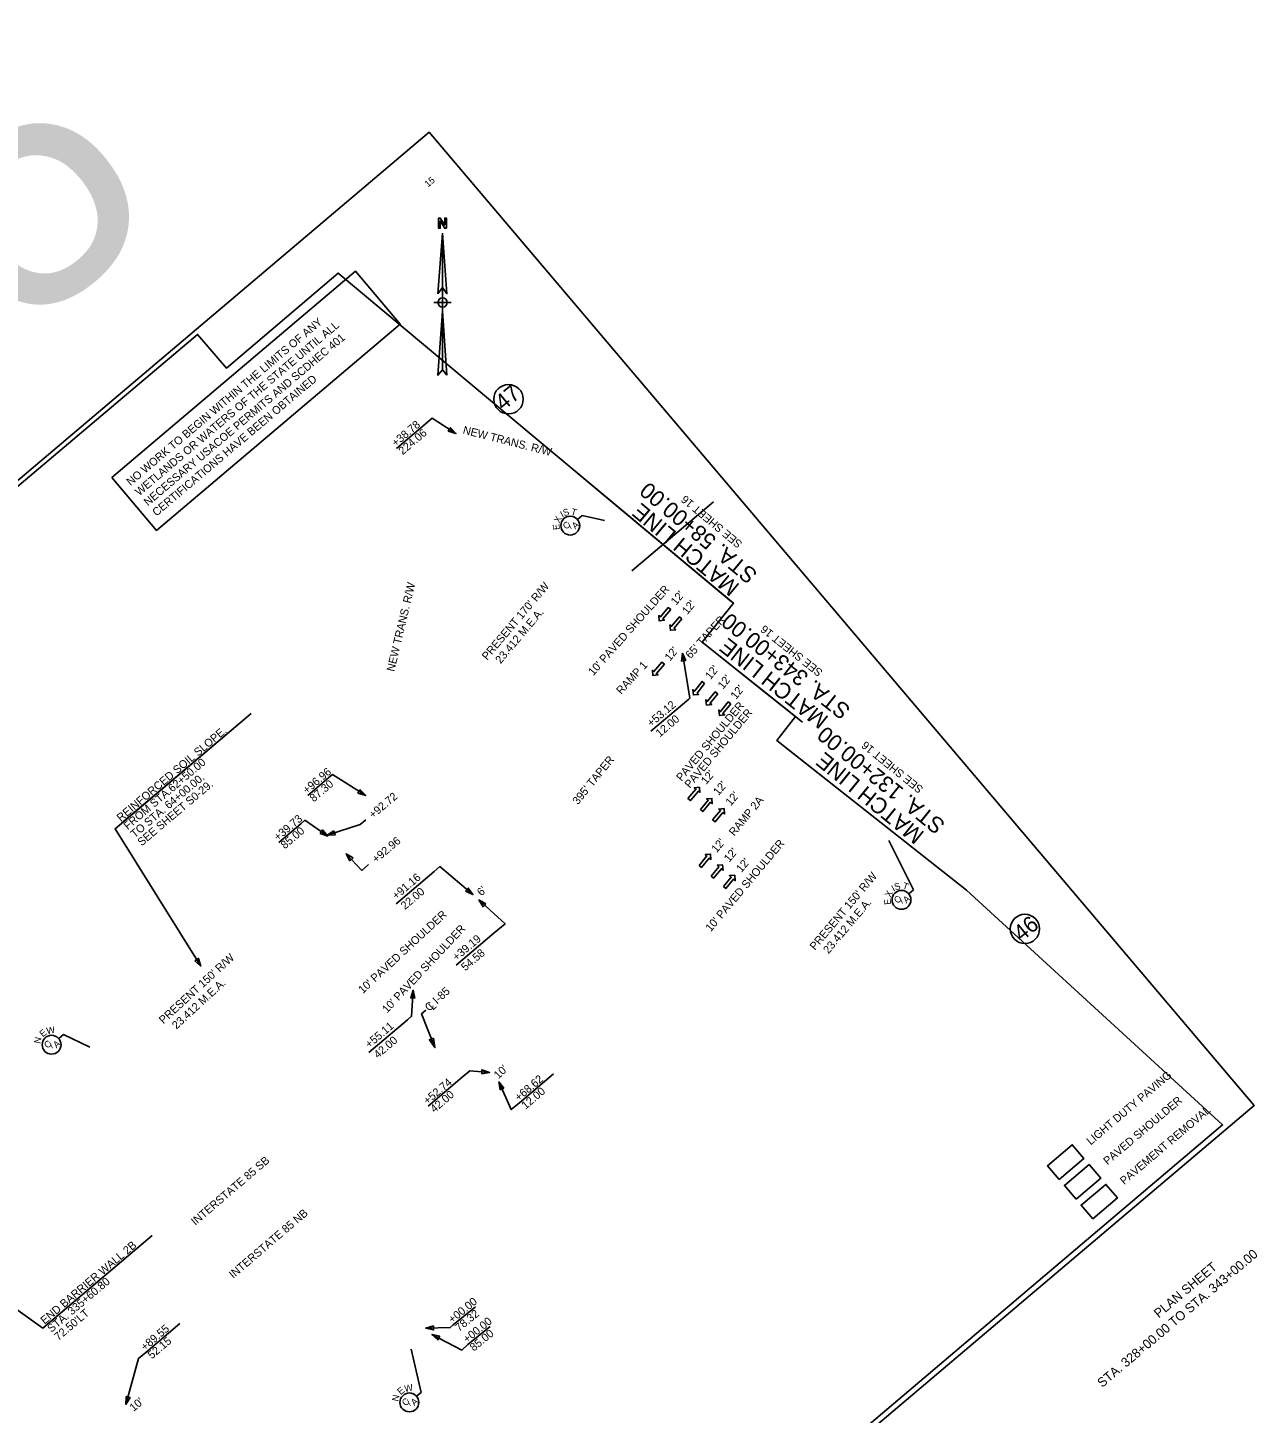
# Model space of a CAD drawing. Extents: x 1613433 to 1615331, y 1095338 to 1097615.
# Drawn here: x 1614410 to 1615331, y 1096576 to 1097615 of the extents above; entities that cross this region are included whole.
import ezdxf

# ---------------------------------------------------------------- set-up
doc = ezdxf.new("R2010")
doc.units = 0
for name, color, linetype in [('RD_EX_Bldg', 7, 'Continuous'), ('RD_EX_BldgApp_txCode', 7, 'Continuous'), ('RD_EX_DR_Pipe', 7, 'Continuous'), ('RD_EX_DV_Prop', 7, 'Continuous'), ('RD_EX_Fence_ChLk', 7, 'Continuous'), ('RD_EX_GuardRail', 7, 'Continuous'), ('RD_EX_H2O', 7, 'Continuous'), ('RD_EX_Misc', 7, 'Continuous'), ('RD_EX_RW', 7, 'Continuous'), ('RD_HC_TX_Rel_Sta50', 7, 'Continuous'), ('RD_PD_Final_TX', 7, 'Continuous'), ('RD_PD_RW_TX', 7, 'Continuous'), ('RD_SHT_DR_TX_FINAL', 7, 'Continuous'), ('RD_SHT_UT_TX_PREL', 7, 'Continuous')]:
    doc.layers.add(name, color=color, linetype=linetype)

msp = doc.modelspace()

# ---------------------------------------------------------------- linework, layer by layer
at = {"layer": 'RD_EX_Bldg'}
for p, q in [((1614704.4, 1097314.6), (1614686.3, 1097299.2)), ((1614635.6, 1097052.4), (1614619.7, 1097038.9)), ((1614614.5, 1097017.8), (1614598, 1097003.8)), ((1614745.4, 1096655.6), (1614728.7, 1096642.1)), ((1614756.4, 1096640.8), (1614739.7, 1096627.3))]:
    msp.add_line(p, q, dxfattribs=at)
for points in [[(1614704.4, 1097314.6), (1614712.9, 1097321.8), (1614730.8, 1097310.3)], [(1614635.6, 1097052.4), (1614638.2, 1097054.6), (1614663.2, 1097038.9)], [(1614614.5, 1097017.8), (1614617.6, 1097020.4), (1614634.8, 1097008.5)], [(1614728.7, 1096642.1), (1614726.6, 1096640), (1614708.2, 1096639.6)], [(1614739.7, 1096627.3), (1614735.2, 1096623.1), (1614712.8, 1096634.8)]]:
    msp.add_lwpolyline(points, dxfattribs=at)
for points in [[(1614725.1, 1097312.1), (1614730.8, 1097310.3), (1614726.8, 1097314.7)], [(1614657.4, 1097040.6), (1614663.2, 1097038.9), (1614659.1, 1097043.3)], [(1614629.1, 1097010.5), (1614634.8, 1097008.5), (1614630.9, 1097013.1)], [(1614713.9, 1096641.3), (1614708.2, 1096639.6), (1614714, 1096638.2)], [(1614718.7, 1096633.5), (1614712.8, 1096634.8), (1614717.2, 1096630.8)]]:
    msp.add_lwpolyline(points, close=True, dxfattribs=at)
at = {"layer": 'RD_EX_BldgApp_txCode'}
for p, q in [((1614433.2, 1096856.7), (1614436.7, 1096859.7)), ((1614436.7, 1096859.7), (1614456.4, 1096850.2)), ((1614704.8, 1096591.4), (1614697.2, 1096623.8)), ((1614701.3, 1096588.5), (1614704.8, 1096591.4))]:
    msp.add_line(p, q, dxfattribs=at)
for centre in [(1614427.8, 1096852.1), (1614695.9, 1096583.9)]:
    msp.add_circle(centre, 7.08, dxfattribs=at)
at = {"layer": 'RD_EX_DR_Pipe'}
msp.add_line((1614862.7, 1097207.4), (1614923.8, 1097259.1), dxfattribs=at)
msp.add_lwpolyline([(1613636.5, 1096424.5), (1613794.6, 1096211.8), (1613781.7, 1096202.2), (1613853.4, 1096105.7), (1613849.9, 1096103.1), (1613959.1, 1095956.1), (1614080.2, 1095752.7), (1615305.3, 1096791.9), (1615113.5, 1096968), (1614971.2, 1097080.2), (1614985.2, 1097098.2), (1614915.3, 1097153.9), (1614938.7, 1097183.2), (1614788.8, 1097308.4), (1614642.5, 1097430.7), (1614558.9, 1097359.3), (1614537.2, 1097384.7), (1613565.8, 1096563.6)], close=True, dxfattribs=at)
msp.add_lwpolyline([(1613636.5, 1096424.5), (1613794.6, 1096211.8), (1613781.7, 1096202.2), (1613853.4, 1096105.7), (1613849.9, 1096103.1), (1613959.1, 1095956.1), (1614080.2, 1095752.7), (1615305.3, 1096791.9), (1615113.5, 1096968), (1614971.2, 1097080.2), (1614985.2, 1097098.2), (1614915.3, 1097153.9), (1614938.7, 1097183.2), (1614788.8, 1097308.4), (1614642.5, 1097430.7), (1614558.9, 1097359.3), (1614537.2, 1097384.7), (1613565.8, 1096563.6)], close=True, dxfattribs=at)
at = {"layer": 'RD_EX_DV_Prop'}
for points in [[(1614663.2, 1097020.6), (1614659, 1097017.1), (1614634.2, 1097009.1)], [(1614665.4, 1096987.1), (1614660.4, 1096982.8), (1614648.5, 1096995.2)]]:
    msp.add_lwpolyline(points, dxfattribs=at)
for points in [[(1614639.2, 1097012.4), (1614634.2, 1097009.1), (1614640.2, 1097009.4)], [(1614653.7, 1096992.1), (1614648.5, 1096995.2), (1614651.4, 1096990)]]:
    msp.add_lwpolyline(points, close=True, dxfattribs=at)
at = {"layer": 'RD_EX_Fence_ChLk'}
for p, q in [((1614821.9, 1097245.8), (1614825.4, 1097248.8)), ((1614825.4, 1097248.8), (1614842.1, 1097245.1)), ((1615073.6, 1096968.3), (1615055.1, 1097005.1)), ((1615070.1, 1096965.3), (1615073.6, 1096968.3))]:
    msp.add_line(p, q, dxfattribs=at)
for centre in [(1614816.5, 1097241.3), (1615064.7, 1096960.7)]:
    msp.add_circle(centre, 7.08, dxfattribs=at)
at = {"layer": 'RD_EX_GuardRail'}
msp.add_lwpolyline([(1613432.5, 1096453.7), (1614710.7, 1097536.3), (1615328.9, 1096806.4), (1614050.7, 1095723.8)], close=True, dxfattribs=at)
at = {"layer": 'RD_EX_H2O'}
for p, q in [((1614720.7, 1097460.5), (1614717.3, 1097415.2)), ((1614720.7, 1097419.8), (1614717.3, 1097415.2)), ((1614720.7, 1097419.8), (1614720.7, 1097402)), ((1614727.3, 1097408.6), (1614714.3, 1097408.6)), ((1614720.7, 1097402), (1614724.1, 1097354.1)), ((1614724.1, 1097354.1), (1614720.7, 1097358))]:
    msp.add_line(p, q, dxfattribs=at)
msp.add_lwpolyline([(1614723.7, 1097464.3), (1614722.4, 1097464.3), (1614719, 1097469.8), (1614719, 1097468.9), (1614719, 1097464.3), (1614717.8, 1097464.3), (1614717.8, 1097471.9), (1614719, 1097471.9), (1614722.4, 1097466.8), (1614722.4, 1097467.2), (1614722.4, 1097471.9), (1614723.7, 1097471.9), (1614723.7, 1097464.3)], dxfattribs=at)
for points in [[(1614720.7, 1097460.5), (1614724.1, 1097415.2), (1614720.7, 1097419.8)], [(1614720.7, 1097402), (1614720.7, 1097358), (1614717.3, 1097354.1)]]:
    msp.add_lwpolyline(points, close=True, dxfattribs=at)
msp.add_circle((1614720.8, 1097408.6), 3.45, dxfattribs=at)
at = {"layer": 'RD_EX_Misc'}
for centre in [(1614770.2, 1097336.1), (1615157.2, 1096938.9)]:
    msp.add_circle(centre, 11, dxfattribs=at)
at = {"layer": 'RD_EX_RW'}
for points in [[(1614891.8, 1097178.4), (1614889.9, 1097179.9), (1614884, 1097172.8), (1614882.8, 1097173.9), (1614883.2, 1097169.9), (1614887.1, 1097170.3), (1614885.9, 1097171.3)], [(1614900.2, 1097171.3), (1614898.3, 1097172.9), (1614892.4, 1097165.8), (1614891.2, 1097166.9), (1614891.6, 1097162.9), (1614895.5, 1097163.2), (1614894.3, 1097164.3)], [(1614887, 1097137.4), (1614885.1, 1097138.9), (1614879.2, 1097131.9), (1614878, 1097132.9), (1614878.4, 1097128.9), (1614882.3, 1097129.3), (1614881.1, 1097130.3)], [(1614917.2, 1097123), (1614915.3, 1097124.5), (1614909.6, 1097117.3), (1614908.3, 1097118.3), (1614908.8, 1097114.4), (1614912.7, 1097114.8), (1614911.5, 1097115.8)], [(1614927, 1097115.3), (1614925.1, 1097116.8), (1614919.4, 1097109.6), (1614918.1, 1097110.7), (1614918.6, 1097106.7), (1614922.5, 1097107.1), (1614921.3, 1097108.1)], [(1614936.7, 1097107.6), (1614934.8, 1097109.1), (1614929.1, 1097101.9), (1614927.8, 1097103), (1614928.2, 1097099), (1614932.2, 1097099.4), (1614930.9, 1097100.4)], [(1614904.7, 1097036.7), (1614906.6, 1097035.2), (1614912.5, 1097042.2), (1614913.7, 1097041.2), (1614913.3, 1097045.1), (1614909.4, 1097044.8), (1614910.6, 1097043.8)], [(1614914, 1097028.4), (1614915.8, 1097026.9), (1614921.7, 1097033.9), (1614922.9, 1097032.9), (1614922.6, 1097036.8), (1614918.6, 1097036.5), (1614919.9, 1097035.4)], [(1614923.2, 1097020.7), (1614925, 1097019.2), (1614930.9, 1097026.2), (1614932.1, 1097025.1), (1614931.8, 1097029.1), (1614927.8, 1097028.8), (1614929.1, 1097027.7)], [(1614913, 1096986.5), (1614914.8, 1096985), (1614920.7, 1096992), (1614921.9, 1096991), (1614921.6, 1096995), (1614917.6, 1096994.6), (1614918.9, 1096993.6)], [(1614922, 1096978.5), (1614923.8, 1096976.9), (1614929.7, 1096984), (1614931, 1096982.9), (1614930.6, 1096986.9), (1614926.6, 1096986.6), (1614927.9, 1096985.5)], [(1614931.2, 1096970.8), (1614933, 1096969.2), (1614938.9, 1096976.3), (1614940.1, 1096975.2), (1614939.8, 1096979.2), (1614935.8, 1096978.9), (1614937.1, 1096977.8)]]:
    msp.add_lwpolyline(points, close=True, dxfattribs=at)
at = {"layer": 'RD_HC_TX_Rel_Sta50'}
msp.add_lwpolyline([(1614715.1, 1096850), (1614705.1, 1096875.2), (1614708.2, 1096878.1)], dxfattribs=at)
msp.add_lwpolyline([(1614714.1, 1096857.1), (1614710.9, 1096855.8), (1614715.1, 1096850)], close=True, dxfattribs=at)
at = {"layer": 'RD_SHT_DR_TX_FINAL'}
for p, q in [((1614937.1, 1097184.5), (1614822.2, 1097280.5)), ((1615113.5, 1096968), (1614975, 1097077.2))]:
    msp.add_line(p, q, dxfattribs=at)
msp.add_lwpolyline([(1614990.4, 1097094), (1614959.1, 1097119), (1614915.3, 1097153.9)], dxfattribs=at)
at = {"layer": 'RD_SHT_UT_TX_PREL'}
for p, q in [((1614905.4, 1097111.3), (1614876.9, 1097087.2)), ((1614577.3, 1097100.4), (1614480.3, 1097018.2)), ((1614714.5, 1096982), (1614685.9, 1096957.8)), ((1614759.5, 1096935.9), (1614731.1, 1096911.8)), ((1614694.4, 1096870.7), (1614665.6, 1096846.3)), ((1614735.6, 1096827.7), (1614710.1, 1096806.1)), ((1614803.9, 1096830.2), (1614778.5, 1096808.6)), ((1614503.1, 1096709), (1614423.2, 1096641.3)), ((1614523.8, 1096643), (1614498.3, 1096621.4))]:
    msp.add_line(p, q, dxfattribs=at)
for points in [[(1614473, 1097277.3), (1614655.6, 1097432), (1614689.1, 1097392.4), (1614506.5, 1097237.7)], [(1614903, 1097140.1), (1614900.5, 1097145.6), (1614899.9, 1097139.6)], [(1614738.1, 1096967.2), (1614743.5, 1096964.6), (1614740.1, 1096969.5)], [(1614753.3, 1096957.8), (1614748, 1096960.6), (1614751.2, 1096955.5)], [(1614535.2, 1096915.1), (1614539.6, 1096911), (1614537.9, 1096916.8)], [(1614700, 1096887), (1614698.8, 1096892.9), (1614696.9, 1096887.2)], [(1614750.1, 1096830.2), (1614756, 1096831.3), (1614750.3, 1096833.3)], [(1614766.8, 1096819.5), (1614763, 1096824.2), (1614764, 1096818.3)], [(1615182.9, 1096751.1), (1615201.4, 1096766.8), (1615192.7, 1096777.1), (1615174.2, 1096761.4)], [(1615195.5, 1096736.3), (1615214, 1096752), (1615205.3, 1096762.3), (1615186.8, 1096746.6)], [(1615208, 1096721.5), (1615226.5, 1096737.2), (1615217.9, 1096747.4), (1615199.3, 1096731.8)], [(1614483.6, 1096588.4), (1614483.5, 1096582.4), (1614486.6, 1096587.6)]]:
    msp.add_lwpolyline(points, close=True, dxfattribs=at)
for points in [[(1614905.4, 1097111.3), (1614906.2, 1097112), (1614900.5, 1097145.6)], [(1614577.3, 1097100.4), (1614475.4, 1097014), (1614539.6, 1096911)], [(1614714.5, 1096982), (1614718.8, 1096985.7), (1614743.5, 1096964.6)], [(1614759.5, 1096935.9), (1614767.6, 1096942.7), (1614748, 1096960.6)], [(1614694.4, 1096870.7), (1614697.6, 1096873.4), (1614698.8, 1096892.9)], [(1614735.6, 1096827.7), (1614741.2, 1096832.4), (1614756, 1096831.3)], [(1614778.5, 1096808.6), (1614772.3, 1096803.5), (1614763, 1096824.2)], [(1615182.9, 1096751.1), (1615201.4, 1096766.8), (1615192.7, 1096777.1), (1615174.2, 1096761.4), (1615182.9, 1096751.1)], [(1615195.5, 1096736.3), (1615214, 1096752), (1615205.3, 1096762.3), (1615186.8, 1096746.6), (1615195.5, 1096736.3)], [(1615208, 1096721.5), (1615226.5, 1096737.2), (1615217.9, 1096747.4), (1615199.3, 1096731.8), (1615208, 1096721.5)], [(1614503.1, 1096709), (1614421.3, 1096639.6), (1614385.8, 1096664.9)], [(1614498.3, 1096621.4), (1614493, 1096616.9), (1614483.5, 1096582.4)]]:
    msp.add_lwpolyline(points, dxfattribs=at)

# ---------------------------------------------------------------- texts
at = {"layer": 'RD_EX_Bldg'}
for s, rotation, p in [('+38.78', 40.265, (1614685.7, 1097300.1)), ('224.06', 40.265, (1614690.9, 1097294)), ('+96.96', 40.265, (1614619.1, 1097039.8)), ('87.30', 40.265, (1614624.3, 1097033.7)), ('+39.73', 40.265, (1614597.4, 1097004.6)), ('85.00', 40.265, (1614602.6, 1096998.5)), ('+00.00', 39.1575, (1614728.1, 1096642.9)), ('78.32', 39.1575, (1614733.2, 1096636.7)), ('+00.00', 39.1575, (1614739.2, 1096628.1)), ('85.00', 39.1575, (1614744.2, 1096621.9))]:
    msp.add_text(s, height=6, rotation=rotation, dxfattribs=at).set_placement(p)
at = {"layer": 'RD_EX_BldgApp_txCode'}
for s, rotation, p in [('W', 11.0644, (1614424.5, 1096859.9)), ('N', 79.1766, (1614419.4, 1096852.6)), ('E', 40.2633, (1614421.3, 1096857.5)), ('C', 40.2634, (1614424.7, 1096849)), ('/', 40.2634, (1614428.3, 1096849.3)), ('A', 40.2634, (1614431.5, 1096849.2)), ('E', 40.2633, (1614689.4, 1096589.3)), ('W', 11.0644, (1614692.7, 1096591.7)), ('N', 79.1766, (1614687.6, 1096584.4)), ('C', 40.2634, (1614692.9, 1096580.8)), ('/', 40.2634, (1614696.5, 1096581.1)), ('A', 40.2634, (1614699.6, 1096581))]:
    msp.add_text(s, height=5, rotation=rotation, dxfattribs=at).set_placement(p)
at = {"layer": 'RD_EX_DV_Prop'}
for s, rotation, p in [("PRESENT 170' R/W ", 49.8309, (1614754.2, 1097140)), ('  23.412 M.E.A.', 49.8309, (1614761.4, 1097133.9)), ('+92.72', 40.265, (1614668.7, 1097021.3)), ('+92.96', 40.265, (1614671.1, 1096988)), ("PRESENT 150' R/W ", 49.8766, (1614999.9, 1096922.5)), ('  23.412 M.E.A.', 49.8766, (1615007.1, 1096916.4)), ("PRESENT 150' R/W ", 42.5813, (1614511.6, 1096867.3)), ('  23.412 M.E.A.', 42.5813, (1614518.1, 1096860.3))]:
    msp.add_text(s, height=6, rotation=rotation, dxfattribs=at).set_placement(p)
at = {"layer": 'RD_EX_Fence_ChLk'}
for s, rotation, p in [('X', 63.4064, (1614808.3, 1097242.9)), ('I', 29.3612, (1614810.6, 1097247.2)), ('S', 17.6407, (1614811.9, 1097248.3)), ('T', 344.1536, (1614816.6, 1097249.6)), ('E', 95.2192, (1614808.7, 1097238.3)), ('C', 40.2618, (1614813.4, 1097238.1)), ('/', 40.2618, (1614817.1, 1097238.5)), ('A', 40.2618, (1614820.2, 1097238.3)), ('X', 63.4064, (1615056.4, 1096962.2)), ('I', 28.2449, (1615058.8, 1096966.7)), ('S', 16.5244, (1615060.1, 1096967.8)), ('T', 341.363, (1615065.1, 1096969.2)), ('E', 96.8935, (1615057, 1096957.4)), ('C', 40.2618, (1615061.6, 1096957.6)), ('/', 40.2618, (1615065.3, 1096957.9)), ('A', 40.2618, (1615068.4, 1096957.8))]:
    msp.add_text(s, height=5, rotation=rotation, dxfattribs=at).set_placement(p)
at = {"layer": 'RD_EX_Misc'}
for s, p in [('47', (1614766.3, 1097327)), ('46', (1615154.8, 1096929.1))]:
    msp.add_text(s, height=12, rotation=39.614, dxfattribs=at).set_placement(p)
at = {"layer": 'RD_HC_TX_Rel_Sta50'}
for s, height, rotation, p in [('RAMP 1', 6, 47.4299, (1614854.7, 1097114.3)), ('RAMP 2A', 6, 50.6135, (1614939.4, 1097008.1)), ('C I-85', 6, 42.6002, (1614710.8, 1096876.7)), ('L', 6, 42.6002, (1614713.6, 1096877.6)), ('INTERSTATE 85 SB', 6, 40.585, (1614535.5, 1096716.3)), ('INTERSTATE 85 NB', 6, 40.585, (1614563.9, 1096676.5)), ('STA. 328+00.00 TO STA. 343+00.00', 6.983, 40.265, (1615215.1, 1096594.7)), ('PLAN SHEET', 6.98, 40.265, (1615257.5, 1096646.8))]:
    msp.add_text(s, height=height, rotation=rotation, dxfattribs=at).set_placement(p)
at = {"layer": 'RD_PD_Final_TX'}
msp.add_text('SHEET 15', height=200, rotation=40.265, dxfattribs=at).set_placement((1613553.3, 1096659.6))
at = {"layer": 'RD_PD_RW_TX'}
for rotation, p in [(345.6709, (1614735.6, 1097310.4)), (76.6319, (1614684.6, 1097131.5))]:
    msp.add_text('NEW TRANS. R/W', height=6, rotation=rotation, dxfattribs=at).set_placement(p)
at = {"layer": 'RD_SHT_DR_TX_FINAL'}
for s, height, rotation, p in [('STA. 58+00.00', 12, 140.1464, (1614957.6, 1097205.9)), ('SEE SHEET 16', 6, 140.1977, (1614945.9, 1097228.5)), ('MATCH LINE', 12, 140.1464, (1614944.1, 1097196.7)), ('STA. 343+00.00', 12, 141.6423, (1615027.4, 1097104.4)), ('SEE SHEET 16', 6, 141.6935, (1615006.2, 1097132.3)), ('MATCH LINE', 12, 141.6423, (1615010.8, 1097097.5)), ('STA. 132+00.00', 12, 140.8967, (1615098.3, 1097018.3)), ('SEE SHEET 16', 6, 140.9479, (1615081.5, 1097044.7)), ('MATCH LINE', 12, 140.8967, (1615082.5, 1097010.9))]:
    msp.add_text(s, height=height, rotation=rotation, dxfattribs=at).set_placement(p)
at = {"layer": 'RD_SHT_UT_TX_PREL'}
for s, height, rotation, p in [('15', 5, 40.265, (1614709.9, 1097494.7)), ('NO WORK TO BEGIN WITHIN THE LIMITS OF ANY', 6, 40.2665, (1614487, 1097270.9)), ('WETLANDS OR WATERS OF THE STATE UNTIL ALL', 6, 40.2665, (1614493.5, 1097263.3)), ('NECESSARY USACOE PERMITS AND SCDHEC 401', 6, 40.2665, (1614500, 1097255.7)), ('CERTIFICATIONS HAVE BEEN OBTAINED', 6, 40.2665, (1614506.4, 1097248)), ("10' PAVED SHOULDER", 6, 48.4867, (1614833.8, 1097128.4)), ("12'", 6, 50.2288, (1614895.8, 1097181.2)), ("12'", 6, 50.2288, (1614904.2, 1097174.2)), ("65' TAPER", 6, 47.9387, (1614906.6, 1097141.1)), ("12'", 6, 50.2288, (1614891.2, 1097139.3)), ("12'", 6, 51.2931, (1614921.6, 1097125.4)), ("12'", 6, 51.2931, (1614931, 1097118.2)), ("12'", 6, 51.2931, (1614940.7, 1097110.6)), ('+53.12', 6, 40.265, (1614877.2, 1097090)), (' PAVED SHOULDER', 6, 50.2758, (1614898.5, 1097047.5)), (' PAVED SHOULDER', 6, 50.2758, (1614904.7, 1097042.3)), ('12.00', 6, 40.265, (1614883.6, 1097082.4)), ('REINFORCED SOIL SLOPE.', 6, 40.265, (1614479.7, 1097019)), ('FROM STA.62+50.00', 6, 40.265, (1614484.9, 1097012.9)), ("395' TAPER", 6, 50.9485, (1614822.2, 1097031.6)), ('TO STA. 64+00.00.', 6, 40.265, (1614490.1, 1097006.8)), ("12'", 6, 50.05, (1614918.4, 1097046.8)), ('SEE SHEET S0-29.', 6, 40.265, (1614495.3, 1097000.7)), ("12'", 6, 50.05, (1614927.6, 1097038.5)), ("12'", 6, 50.05, (1614936.8, 1097030.7)), ("10' PAVED SHOULDER", 6, 50.0516, (1614921.8, 1096936.4)), ("12'", 6, 50.05, (1614926.2, 1096995.6)), ("12'", 6, 50.05, (1614935.6, 1096988.5)), ("12'", 6, 50.05, (1614944.8, 1096980.8)), ('+91.16', 6, 40.265, (1614686.1, 1096960.6)), ('22.00', 6, 40.265, (1614692.6, 1096953)), ("6'", 6, 44.5344, (1614750, 1096963.2)), ("10' PAVED SHOULDER", 6, 42.8816, (1614661, 1096890)), ("10' PAVED SHOULDER", 6, 46.9403, (1614679.2, 1096875.4)), ('+39.19', 6, 40.265, (1614731.3, 1096914.6)), ('54.58', 6, 40.265, (1614737.8, 1096907)), ('+55.11', 6, 40.265, (1614665.9, 1096849.2)), ('42.00', 6, 40.265, (1614672.3, 1096841.5)), ("10'", 6, 43.6329, (1614762.6, 1096826)), ('+52.74', 6, 40.265, (1614709.5, 1096806.9)), ('+68.62', 6, 40.265, (1614777.9, 1096809.4)), ('LIGHT DUTY PAVING', 6, 40.265, (1615206.5, 1096776.5)), ('42.00', 6, 40.265, (1614714.7, 1096800.8)), ('12.00', 6, 40.265, (1614783, 1096803.3)), ('PAVED SHOULDER', 6, 40.265, (1615219.1, 1096761.6)), ('PAVEMENT REMOVAL', 6, 40.265, (1615231.6, 1096746.8)), ('END BARRIER WALL 2B', 6, 40.265, (1614422.6, 1096642.1)), ('STA. 335+60.80', 6, 40.265, (1614427.7, 1096636)), ("72.50'LT", 6, 40.265, (1614432.9, 1096629.9)), ('+89.55', 6, 40.265, (1614497.7, 1096622.2)), ('52.15', 6, 40.265, (1614502.9, 1096616.1)), ("10'", 6, 40.265, (1614489.3, 1096576.7))]:
    msp.add_text(s, height=height, rotation=rotation, dxfattribs=at).set_placement(p)

doc.saveas('drawing.dxf')
